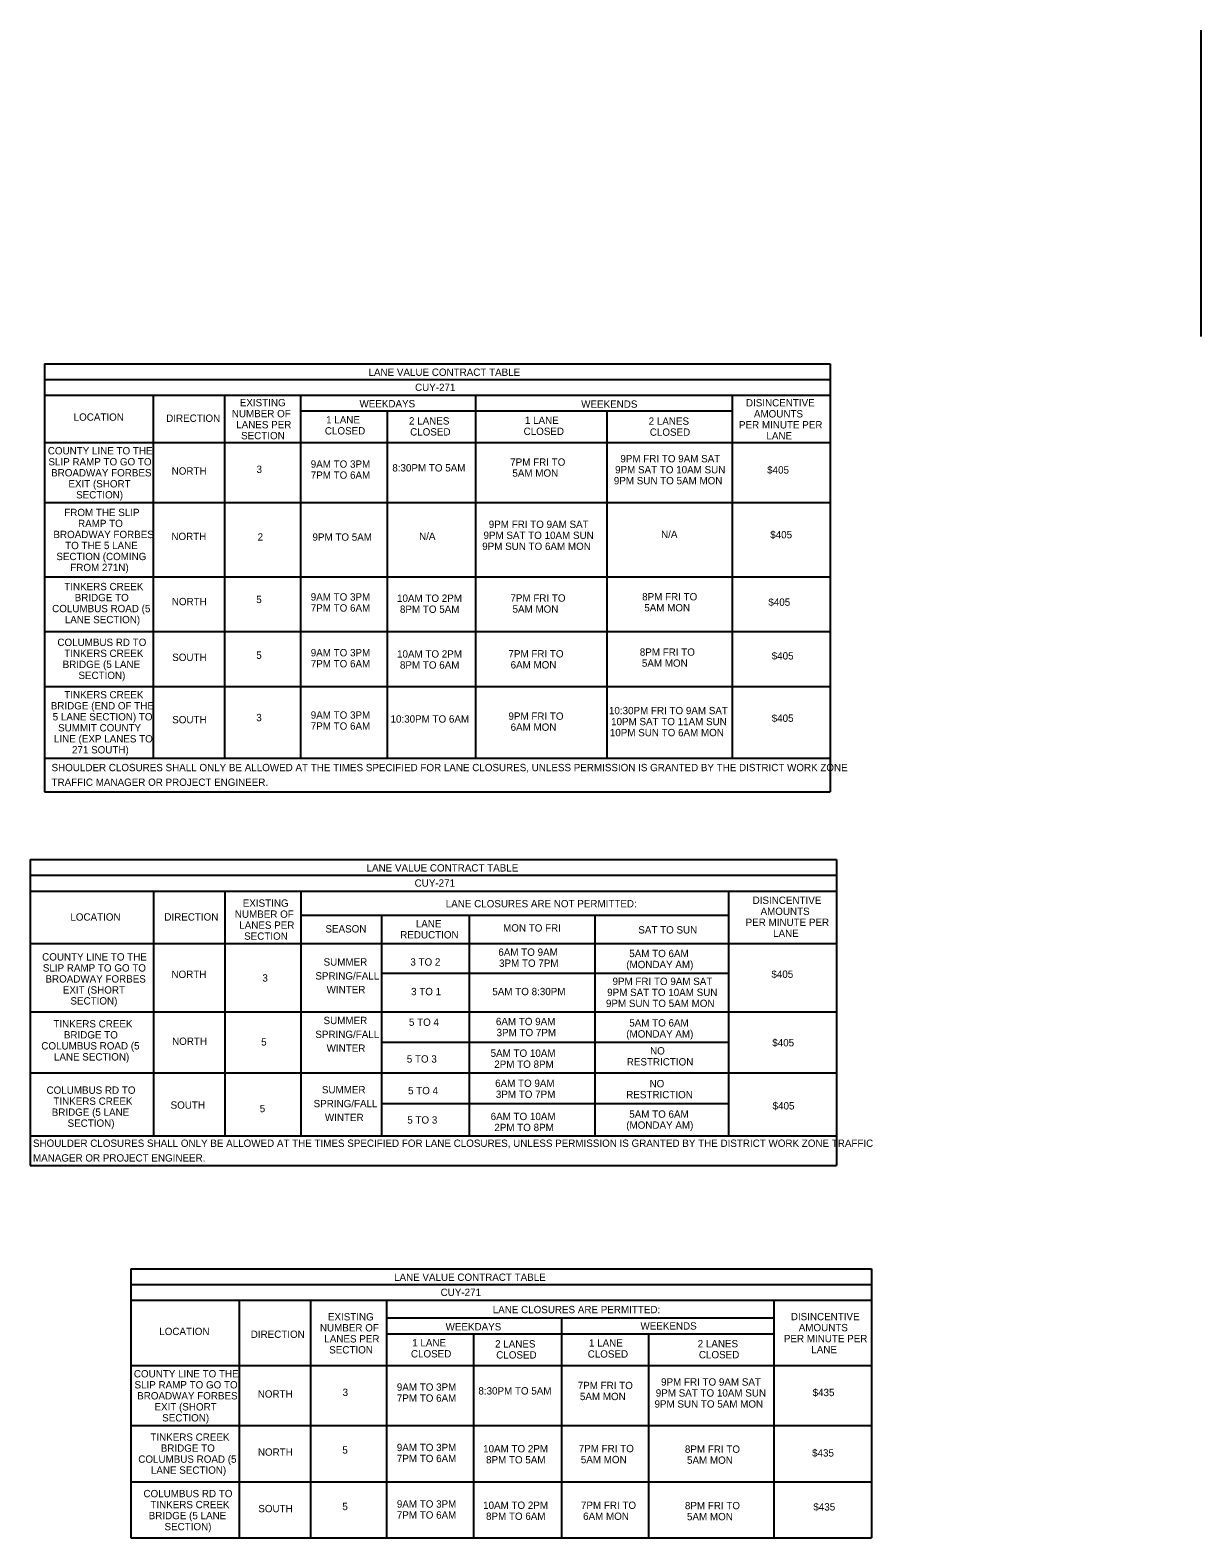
# Model space of a CAD drawing. Extents: x 0 to 49.3, y -31.9 to 22.
# Drawn here: x 4.34 to 26.66, y -31.95 to -3.18 of the extents above; entities that cross this region are included whole.
import ezdxf

# ---------------------------------------------------------------- set-up
doc = ezdxf.new("R2010")
doc.units = 0
doc.layers.add('SH_Text', color=7, linetype='Continuous')

msp = doc.modelspace()

# ---------------------------------------------------------------- linework, layer by layer
at = {"layer": 'SH_Text'}
for p, q in [((26.656, -3.182), (26.656, -9.028)), ((4.614, -9.549), (4.614, -17.711)), ((4.614, -9.549), (19.589, -9.549)), ((19.589, -9.549), (19.589, -17.711)), ((4.614, -9.849), (19.589, -9.849)), ((4.614, -10.149), (19.589, -10.149)), ((6.682, -10.149), (6.682, -17.068)), ((8.042, -10.149), (8.042, -17.068)), ((9.49, -10.149), (9.49, -17.068)), ((12.827, -10.149), (12.827, -17.068)), ((17.724, -10.149), (17.724, -17.068)), ((9.49, -10.446), (17.724, -10.446)), ((11.146, -10.446), (11.146, -17.068)), ((15.334, -10.446), (15.334, -17.068)), ((4.614, -11.049), (19.589, -11.049)), ((4.614, -12.195), (19.589, -12.195)), ((4.614, -13.613), (19.589, -13.613)), ((4.614, -14.655), (19.589, -14.655)), ((4.614, -15.705), (19.589, -15.705)), ((4.614, -17.068), (19.589, -17.068)), ((4.614, -17.711), (19.589, -17.711)), ((4.338, -19.002), (19.709, -19.002)), ((4.338, -19.002), (4.338, -24.842)), ((19.709, -19.002), (19.709, -24.842)), ((4.338, -19.302), (19.709, -19.302)), ((4.338, -19.609), (19.709, -19.609)), ((6.69, -19.609), (6.69, -24.279)), ((8.05, -19.609), (8.05, -24.279)), ((9.498, -19.609), (9.498, -24.279)), ((17.65, -19.609), (17.65, -24.279)), ((9.498, -20.064), (17.65, -20.064)), ((11.038, -20.071), (11.038, -24.279)), ((12.704, -20.071), (12.704, -24.279)), ((15.103, -20.08), (15.103, -24.279)), ((4.338, -20.609), (19.709, -20.609)), ((11.038, -21.17), (17.65, -21.17)), ((4.338, -21.91), (19.709, -21.91)), ((11.038, -22.489), (17.65, -22.489)), ((4.338, -23.075), (19.709, -23.075)), ((11.038, -23.661), (17.65, -23.661)), ((4.338, -24.279), (19.709, -24.279)), ((4.338, -24.842), (19.709, -24.842)), ((6.255, -26.814), (20.379, -26.814)), ((6.255, -26.814), (6.255, -31.945)), ((20.379, -26.814), (20.379, -31.945)), ((6.255, -27.114), (20.379, -27.114)), ((6.255, -27.414), (20.379, -27.414)), ((8.323, -27.414), (8.323, -31.945)), ((9.683, -27.414), (9.683, -31.945)), ((11.131, -27.414), (11.131, -31.945)), ((18.514, -27.414), (18.514, -31.945)), ((11.131, -27.748), (18.514, -27.748)), ((14.468, -27.748), (14.468, -31.945)), ((11.131, -28.055), (18.514, -28.055)), ((12.787, -28.055), (12.787, -31.945)), ((16.125, -28.055), (16.125, -31.945)), ((6.255, -28.658), (20.379, -28.658)), ((6.255, -29.804), (20.379, -29.804)), ((6.255, -30.88), (20.379, -30.88)), ((6.255, -31.945), (20.379, -31.945))]:
    msp.add_line(p, q, dxfattribs=at)

# ---------------------------------------------------------------- texts
for s, p in [('LANE VALUE CONTRACT TABLE', (10.788, -9.778)), ('CUY-271', (11.675, -10.066)), ('EXISTING ', (8.334, -10.358)), ('WEEKDAYS', (10.616, -10.379)), ('WEEKENDS', (14.843, -10.386)), ('DISINCENTIVE ', (17.984, -10.361)), ('LOCATION', (5.167, -10.634)), ('DIRECTION', (6.931, -10.655)), ('NUMBER OF', (8.182, -10.568)), ('LANES PER ', (8.266, -10.778)), ('1 LANE', (9.98, -10.686)), ('2 LANES ', (11.56, -10.706)), ('1 LANE', (13.769, -10.695)), ('2 LANES ', (16.129, -10.711)), ('PER MINUTE PER ', (17.851, -10.781)), ('AMOUNTS', (18.136, -10.571)), ('SECTION', (8.359, -10.988)), ('CLOSED', (9.956, -10.896)), ('CLOSED', (11.582, -10.916)), ('CLOSED', (13.745, -10.905)), ('CLOSED', (16.151, -10.921)), ('LANE', (18.374, -10.991)), ('COUNTY LINE TO THE ', (4.674, -11.276)), ('SLIP RAMP TO GO TO ', (4.686, -11.486)), ('3', (8.653, -11.63)), ('9AM TO 3PM', (9.687, -11.53)), ('8:30PM TO 5AM', (11.242, -11.602)), ('7PM FRI TO ', (13.49, -11.492)), ('9PM SAT TO 10AM SUN', (15.489, -11.637)), ('9PM FRI TO 9AM SAT', (15.59, -11.427)), ('$405', (18.388, -11.642)), ('BROADWAY FORBES ', (4.737, -11.696)), ('EXIT (SHORT ', (5.067, -11.906)), ('NORTH', (7.035, -11.662)), ('7PM TO 6AM', (9.687, -11.74)), ('5AM MON', (13.531, -11.702)), ('9PM SUN TO 5AM MON', (15.465, -11.847)), ('SECTION)', (5.214, -12.116)), ('FROM THE SLIP ', (4.988, -12.453)), ('RAMP TO ', (5.251, -12.663)), ('9PM FRI TO 9AM SAT', (13.081, -12.679)), ('BROADWAY FORBES ', (4.781, -12.873)), ('TO THE 5 LANE ', (5.005, -13.083)), ('NORTH', (7.03, -12.91)), ('2', (8.674, -12.921)), ('9PM TO 5AM', (9.72, -12.923)), ('N/A', (11.752, -12.906)), ('9PM SAT TO 10AM SUN', (12.98, -12.889)), ('N/A', (16.366, -12.869)), ('$405', (18.447, -12.878)), ('SECTION (COMING ', (4.837, -13.293)), ('9PM SUN TO 6AM MON', (12.956, -13.099)), ('FROM 271N)', (5.103, -13.503)), ('TINKERS CREEK ', (4.988, -13.867)), ('BRIDGE TO ', (5.187, -14.077)), ('NORTH', (7.038, -14.153)), ('5', (8.648, -14.113)), ('9AM TO 3PM', (9.687, -14.065)), ('10AM TO 2PM', (11.332, -14.089)), ('7PM FRI TO ', (13.494, -14.086)), ('8PM FRI TO ', (16.005, -14.061)), ('$405', (18.411, -14.164)), ('COLUMBUS ROAD (5 ', (4.757, -14.287)), ('LANE SECTION)', (4.998, -14.497)), ('7PM TO 6AM', (9.687, -14.275)), ('8PM TO 5AM', (11.388, -14.299)), ('5AM MON', (13.534, -14.296)), ('5AM MON', (16.045, -14.271)), ('COLUMBUS RD TO ', (4.857, -14.931)), ('BRIDGE (5 LANE ', (4.957, -15.351)), ('TINKERS CREEK ', (4.988, -15.141)), ('SOUTH', (7.046, -15.217)), ('5', (8.648, -15.176)), ('9AM TO 3PM', (9.687, -15.129)), ('7PM TO 6AM', (9.687, -15.339)), ('10AM TO 2PM', (11.332, -15.153)), ('8PM TO 6AM', (11.388, -15.363)), ('7PM FRI TO ', (13.456, -15.15)), ('6AM MON', (13.497, -15.36)), ('8PM FRI TO ', (15.96, -15.117)), ('5AM MON', (16, -15.327)), ('$405', (18.475, -15.189)), ('SECTION)', (5.258, -15.561)), ('TINKERS CREEK ', (4.988, -15.931)), ('BRIDGE (END OF THE ', (4.731, -16.141)), ('10:30PM FRI TO 9AM SAT', (15.372, -16.233)), ('5 LANE SECTION) TO ', (4.767, -16.351)), ('SOUTH', (7.046, -16.406)), ('3', (8.649, -16.366)), ('9AM TO 3PM', (9.687, -16.318)), ('7PM TO 6AM', (9.687, -16.528)), ('10:30PM TO 6AM', (11.208, -16.393)), ('9PM FRI TO ', (13.456, -16.339)), ('10PM SAT TO 11AM SUN', (15.413, -16.443)), ('$405', (18.475, -16.378)), ('LINE (EXP LANES TO ', (4.792, -16.771)), ('SUMMIT COUNTY ', (4.871, -16.561)), ('6AM MON', (13.497, -16.549)), ('10PM SUN TO 6AM MON', (15.389, -16.653)), ('271 SOUTH)', (5.135, -16.981)), ('SHOULDER CLOSURES SHALL ONLY BE ALLOWED AT THE TIMES SPECIFIED FOR LANE CLOSURES, UNLESS PERMISSION IS GRANTED BY THE DISTRICT WORK ZONE ', (4.745, -17.32)), ('TRAFFIC MANAGER OR PROJECT ENGINEER.', (4.745, -17.6)), ('LANE VALUE CONTRACT TABLE', (10.751, -19.234)), ('CUY-271', (11.667, -19.523)), ('EXISTING ', (8.391, -19.906)), ('LANE CLOSURES ARE NOT PERMITTED: ', (12.261, -19.917)), ('DISINCENTIVE ', (18.111, -19.852)), ('LOCATION', (5.104, -20.171)), ('DIRECTION', (6.896, -20.17)), ('NUMBER OF', (8.24, -20.116)), ('PER MINUTE PER ', (17.978, -20.272)), ('AMOUNTS', (18.262, -20.062)), ('LANES PER ', (8.324, -20.326)), ('SECTION', (8.417, -20.536)), ('SEASON', (9.967, -20.397)), ('REDUCTION', (11.393, -20.51)), ('LANE ', (11.69, -20.3)), ('MON TO FRI', (13.354, -20.379)), ('SAT TO SUN', (15.932, -20.416)), ('LANE', (18.501, -20.482)), ('6AM TO 9AM', (13.263, -20.842)), ('COUNTY LINE TO THE ', (4.566, -20.932)), ('SUMMER', (9.932, -21.029)), ('3 TO 2', (11.586, -21.029)), ('3PM TO 7PM', (13.277, -21.052)), ('(MONDAY AM)', (15.702, -21.077)), ('5AM TO 6AM ', (15.759, -20.867)), ('SLIP RAMP TO GO TO ', (4.579, -21.142)), ('BROADWAY FORBES ', (4.629, -21.352)), ('NORTH', (7.032, -21.264)), ('3', (8.765, -21.333)), ('SPRING/FALL', (9.775, -21.294)), ('9PM FRI TO 9AM SAT', (15.44, -21.399)), ('$405', (18.469, -21.262)), ('EXIT (SHORT ', (4.96, -21.562)), ('WINTER', (9.99, -21.557)), ('3 TO 1', (11.6, -21.593)), ('5AM TO 8:30PM', (13.149, -21.593)), ('9PM SAT TO 10AM SUN', (15.338, -21.609)), ('SECTION)', (5.106, -21.771)), ('9PM SUN TO 5AM MON', (15.315, -21.819)), ('TINKERS CREEK ', (4.78, -22.209)), ('SUMMER', (9.932, -22.145)), ('5 TO 4', (11.559, -22.178)), ('6AM TO 9AM ', (13.217, -22.165)), ('5AM TO 6AM ', (15.759, -22.191)), ('BRIDGE TO ', (4.98, -22.419)), ('NORTH', (7.043, -22.541)), ('5', (8.741, -22.554)), ('SPRING/FALL', (9.775, -22.41)), ('3PM TO 7PM', (13.23, -22.375)), ('(MONDAY AM)', (15.702, -22.401)), ('$405', (18.486, -22.569)), ('COLUMBUS ROAD (5 ', (4.55, -22.629)), ('LANE SECTION)', (4.791, -22.839)), ('WINTER', (9.99, -22.673)), ('5AM TO 10AM', (13.116, -22.769)), ('NO ', (16.156, -22.724)), ('5 TO 3', (11.518, -22.879)), ('2PM TO 8PM', (13.186, -22.979)), ('RESTRICTION', (15.712, -22.934)), ('6AM TO 9AM', (13.202, -23.343)), ('NO ', (16.146, -23.35)), ('COLUMBUS RD TO ', (4.65, -23.474)), ('TINKERS CREEK ', (4.78, -23.684)), ('SPRING/FALL', (9.742, -23.731)), ('SUMMER', (9.899, -23.466)), ('5 TO 4', (11.542, -23.483)), ('3PM TO 7PM', (13.216, -23.553)), ('RESTRICTION', (15.702, -23.56)), ('BRIDGE (5 LANE ', (4.749, -23.894)), ('SOUTH', (7.015, -23.759)), ('5', (8.714, -23.825)), ('WINTER', (9.957, -23.994)), ('6AM TO 10AM', (13.117, -23.976)), ('5AM TO 6AM ', (15.759, -23.931)), ('$405', (18.492, -23.773)), ('SECTION)', (5.051, -24.104)), ('5 TO 3', (11.527, -24.043)), ('2PM TO 8PM', (13.187, -24.186)), ('(MONDAY AM)', (15.702, -24.141)), ('SHOULDER CLOSURES SHALL ONLY BE ALLOWED AT THE TIMES SPECIFIED FOR LANE CLOSURES, UNLESS PERMISSION IS GRANTED BY THE DISTRICT WORK ZONE TRAFFIC ', (4.391, -24.487)), ('MANAGER OR PROJECT ENGINEER.', (4.391, -24.767)), ('LANE VALUE CONTRACT TABLE', (11.275, -27.043)), ('CUY-271', (12.163, -27.331)), ('LANE CLOSURES ARE PERMITTED: ', (13.156, -27.66)), ('NUMBER OF', (9.862, -28.008)), ('EXISTING ', (10.014, -27.798)), ('WEEKDAYS', (12.258, -27.988)), ('WEEKENDS', (15.973, -27.973)), ('DISINCENTIVE ', (18.84, -27.794)), ('AMOUNTS', (18.991, -28.004)), ('LOCATION', (6.799, -28.077)), ('DIRECTION', (8.543, -28.131)), ('LANES PER ', (9.946, -28.218)), ('1 LANE', (11.621, -28.294)), ('2 LANES ', (13.201, -28.315)), ('1 LANE', (14.991, -28.297)), ('2 LANES ', (17.064, -28.311)), ('PER MINUTE PER ', (18.707, -28.214)), ('SECTION', (10.039, -28.428)), ('CLOSED', (11.597, -28.504)), ('CLOSED', (13.223, -28.525)), ('CLOSED', (14.967, -28.507)), ('CLOSED', (17.087, -28.521)), ('LANE', (19.23, -28.424)), ('COUNTY LINE TO THE ', (6.315, -28.885)), ('SLIP RAMP TO GO TO ', (6.327, -29.095)), ('9AM TO 3PM', (11.328, -29.139)), ('7PM FRI TO ', (14.777, -29.108)), ('9PM FRI TO 9AM SAT', (16.366, -29.041)), ('BROADWAY FORBES ', (6.378, -29.305)), ('NORTH', (8.676, -29.27)), ('3', (10.294, -29.239)), ('7PM TO 6AM', (11.328, -29.349)), ('8:30PM TO 5AM', (12.883, -29.211)), ('5AM MON', (14.818, -29.318)), ('9PM SUN TO 5AM MON', (16.241, -29.461)), ('9PM SAT TO 10AM SUN', (16.265, -29.251)), ('$435', (19.255, -29.242)), ('EXIT (SHORT ', (6.708, -29.515)), ('SECTION)', (6.855, -29.725)), ('TINKERS CREEK ', (6.629, -30.093)), ('BRIDGE TO ', (6.828, -30.303)), ('5', (10.289, -30.339)), ('9AM TO 3PM', (11.328, -30.291)), ('10AM TO 2PM', (12.973, -30.315)), ('7PM FRI TO ', (14.796, -30.312)), ('8PM FRI TO ', (16.82, -30.323)), ('COLUMBUS ROAD (5 ', (6.399, -30.513)), ('NORTH', (8.679, -30.379)), ('7PM TO 6AM', (11.328, -30.501)), ('8PM TO 5AM', (13.029, -30.525)), ('5AM MON', (14.836, -30.522)), ('5AM MON', (16.86, -30.533)), ('$435', (19.245, -30.395)), ('LANE SECTION)', (6.639, -30.723)), ('COLUMBUS RD TO ', (6.498, -31.171)), ('TINKERS CREEK ', (6.629, -31.381)), ('SOUTH', (8.687, -31.457)), ('5', (10.289, -31.417)), ('9AM TO 3PM', (11.328, -31.369)), ('10AM TO 2PM', (12.973, -31.393)), ('7PM FRI TO ', (14.838, -31.393)), ('8PM FRI TO ', (16.82, -31.4)), ('$435', (19.269, -31.424)), ('BRIDGE (5 LANE ', (6.598, -31.591)), ('7PM TO 6AM', (11.328, -31.579)), ('8PM TO 6AM', (13.029, -31.603)), ('6AM MON', (14.879, -31.603)), ('5AM MON', (16.86, -31.61)), ('SECTION)', (6.899, -31.801))]:
    msp.add_text(s, height=0.14, dxfattribs=at).set_placement(p)

doc.saveas('drawing.dxf')
